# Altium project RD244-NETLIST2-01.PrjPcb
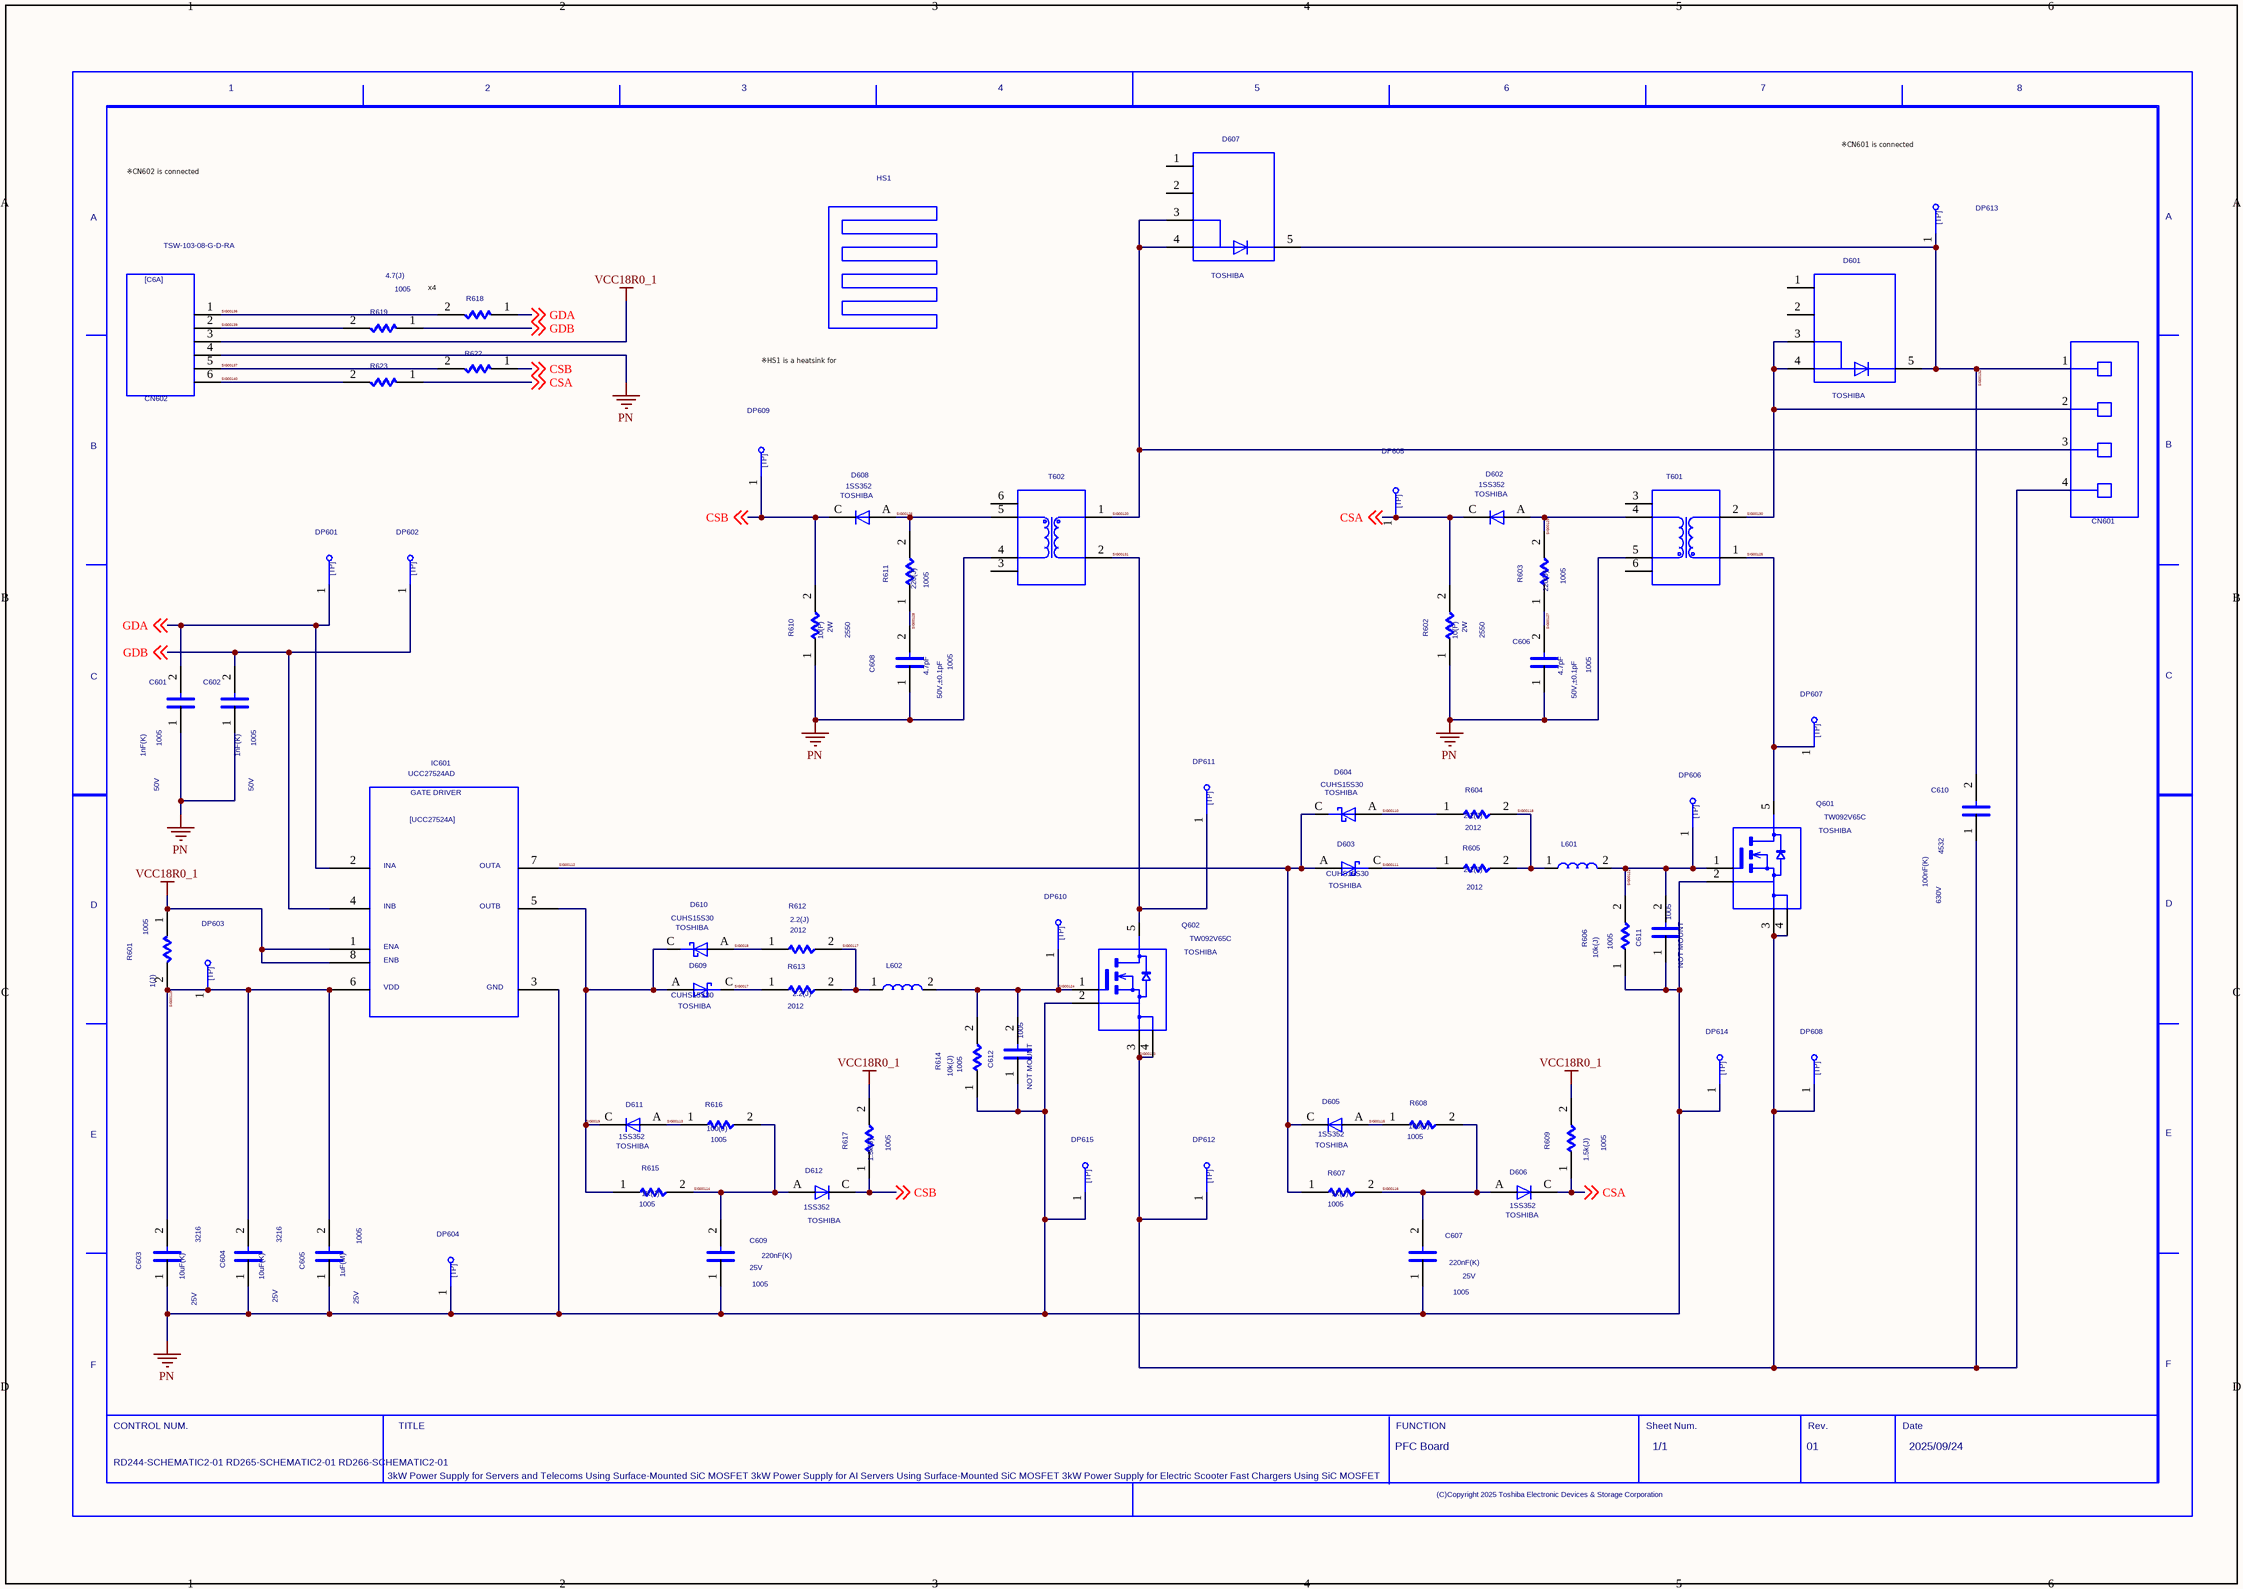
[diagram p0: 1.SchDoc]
1 sheet, 71 parts. Net scope: global (net labels, ports and power ports of the same name join across sheets).

## Sheet 1.SchDoc
size 420 x 297 mm

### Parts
C601  VAL1: 1nF(K)  VAL2: 50V  SIZECODESMD: 1005  (hidden comment: C)
C602  VAL1: 1nF(K)  VAL2: 50V  SIZECODESMD: 1005  (hidden comment: C)
C603  VAL1: 10uF(K)  VAL2: 25V  SIZECODESMD: 3216  (hidden comment: C)
C604  VAL1: 10uF(K)  VAL2: 25V  SIZECODESMD: 3216  (hidden comment: C)
C605  VAL1: 1uF(M)  VAL2: 25V  SIZECODESMD: 1005  (hidden comment: C)
C606  VAL1: 4.7pF  VAL2: 50V,±0.1pF  SIZECODESMD: 1005  (hidden comment: C)
C607  VAL1: 220nF(K)  VAL2: 25V  SIZECODESMD: 1005  (hidden comment: C)
C608  VAL1: 4.7pF  VAL2: 50V,±0.1pF  SIZECODESMD: 1005  (hidden comment: C)
C609  VAL1: 220nF(K)  VAL2: 25V  SIZECODESMD: 1005  (hidden comment: C)
C610  VAL1: 100nF(K)  VAL2: 630V  SIZECODESMD: 4532  (hidden comment: C)
C611  NOTMOUNT: NOT MOUNT  SIZECODESMD: 1005  (hidden comment: C)
C612  NOTMOUNT: NOT MOUNT  SIZECODESMD: 1005  (hidden comment: C)
CN601  RD-244_CN_from_PFC  (value not drawn)
CN602  VAL3: TSW-103-08-G-D-RA  (hidden comment: C6A)
D601  USERCOMPTEXT3: TOSHIBA  (hidden comment: TRS12V65H)
D602  USERCOMPTEXT3: TOSHIBA  VAL3: 1SS352  (hidden comment: D)
D603  USERCOMPTEXT3: TOSHIBA  (hidden comment: CUHS15S30)
D604  USERCOMPTEXT3: TOSHIBA  (hidden comment: CUHS15S30)
D605  USERCOMPTEXT3: TOSHIBA  VAL3: 1SS352  (hidden comment: D)
D606  USERCOMPTEXT3: TOSHIBA  VAL3: 1SS352  (hidden comment: D)
D607  USERCOMPTEXT3: TOSHIBA  (hidden comment: TRS12V65H)
D608  USERCOMPTEXT3: TOSHIBA  VAL3: 1SS352  (hidden comment: D)
D609  USERCOMPTEXT3: TOSHIBA  (hidden comment: CUHS15S30)
D610  USERCOMPTEXT3: TOSHIBA  (hidden comment: CUHS15S30)
D611  USERCOMPTEXT3: TOSHIBA  VAL3: 1SS352  (hidden comment: D)
D612  USERCOMPTEXT3: TOSHIBA  VAL3: 1SS352  (hidden comment: D)
DP601  TP  (value not drawn)
DP602  TP  (value not drawn)
DP603  TP  (value not drawn)
DP604  TP  (value not drawn)
DP605  TP  (value not drawn)
DP606  TP  (value not drawn)
DP607  TP  (value not drawn)
DP608  TP  (value not drawn)
DP609  TP  (value not drawn)
DP610  TP  (value not drawn)
DP611  TP  (value not drawn)
DP612  TP  (value not drawn)
DP613  TP  (value not drawn)
DP614  TP  (value not drawn)
DP615  TP  (value not drawn)
HS1  UB4060-12BM-1GG  (value not drawn)
IC601  VAL3: UCC27524AD  (hidden comment: L27524)
L601  L  (value not drawn)
L602  L  (value not drawn)
Q601  VAL3: TW092V65C  USERCOMPTEXT3: TOSHIBA  (hidden comment: NchMOSFET_DFN8x8-02)
Q602  VAL3: TW092V65C  USERCOMPTEXT3: TOSHIBA  (hidden comment: NchMOSFET_DFN8x8-02)
R601  VAL1: 1(J)  SIZECODESMD: 1005  (hidden comment: R)
R602  VAL2: 2W  USERCOMPTEXT1: 10(F)  SIZECODESMD: 2550  (hidden comment: R)
R603  VAL1: 220(J)  SIZECODESMD: 1005  (hidden comment: R)
R604  VAL1: 2.2(J)  SIZECODESMD: 2012  (hidden comment: R)
R605  VAL1: 2.2(J)  SIZECODESMD: 2012  (hidden comment: R)
R606  VAL1: 10k(J)  SIZECODESMD: 1005  (hidden comment: R)
R607  VAL1: 1k(J)  SIZECODESMD: 1005  (hidden comment: R)
R608  VAL1: 100(J)  SIZECODESMD: 1005  (hidden comment: R)
R609  VAL1: 1.5k(J)  SIZECODESMD: 1005  (hidden comment: R)
R610  VAL2: 2W  USERCOMPTEXT1: 10(F)  SIZECODESMD: 2550  (hidden comment: R)
R611  VAL1: 220(J)  SIZECODESMD: 1005  (hidden comment: R)
R612  VAL1: 2.2(J)  SIZECODESMD: 2012  (hidden comment: R)
R613  VAL1: 2.2(J)  SIZECODESMD: 2012  (hidden comment: R)
R614  VAL1: 10k(J)  SIZECODESMD: 1005  (hidden comment: R)
R615  VAL1: 1K(J)  SIZECODESMD: 1005  (hidden comment: R)
R616  VAL1: 100(J)  SIZECODESMD: 1005  (hidden comment: R)
R617  VAL1: 1.5k(J)  SIZECODESMD: 1005  (hidden comment: R)
R618  VAL1: 4.7(J)  SIZECODESMD: 1005  (hidden comment: R)
R619  R  (value not drawn)
R622  R  (value not drawn)
R623  R  (value not drawn)
T601  PH9505_100NLT  (value not drawn)
T602  PH9505_100NLT  (value not drawn)
U?  DATE: 2025/09/24  DRAWINGNUMBER: RD244-SCHEMATIC2-01 / RD265-SCHEMATIC2-01 / RD266-SCHEMATIC2-01  TITLE: 3kW Power Supply for Servers and Telecoms Using Surface-Mounted SiC MOSFET / 3kW Power Supply for AI Servers Using Surface-Mounted SiC MOSFET / 3kW Power Supply for Electric Scooter Fast Chargers Using SiC MOSFET  FUNCTION: PFC Board  SHEETNUMBER: 1/1  REVISION: 01  (hidden comment: WAKU_DEF100)

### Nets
PN: C601.1 C602.1 C603.1 C604.1 C605.1 C606.1 C607.1 C608.1 C609.1 C611.1 C612.1 CN602.4 DP604.1 DP614.1 DP615.1 IC601.3 Q601.2 Q602.2 R602.1 R606.1 R610.1 R614.1 T601.5 T602.4
VCC18R0_1: CN602.3 IC601.1 IC601.8 R601.1 R609.2 R617.2
CSA: D602.C D606.C DP605.1 R602.2 R609.1 R623.1 ; off-sheet CSA
CSB: D608.C D612.C DP609.1 R610.2 R617.1 R622.1 ; off-sheet CSB
GDA: C601.2 DP601.1 IC601.2 R618.1 ; off-sheet GDA
GDB: C602.2 DP602.1 IC601.4 R619.1 ; off-sheet GDB
SIG0017: D609.C R613.1
SIG0018: D610.A R612.1
SIG0019: D609.A D610.C D611.C IC601.5 R615.1
SIG00110: D604.A R604.1
SIG00111: D603.C R605.1
SIG00112: D603.A D604.C D605.C IC601.7 R607.1
SIG00113: D611.A R616.1
SIG00114: C609.2 D612.A R615.2 R616.2
SIG00115: D605.A R608.1
SIG00116: C607.2 D606.A R607.2 R608.2
SIG00117: L602.1 R612.2 R613.2
SIG00118: L601.1 R604.2 R605.2
SIG00119: C603.2 C604.2 C605.2 DP603.1 IC601.6 R601.2
SIG00120: CN601.3 D607.3 D607.4 T602.1
SIG00121: C611.2 DP606.1 L601.2 Q601.1 R606.2
SIG00124: C612.2 DP610.1 L602.2 Q602.1 R614.2
SIG00125: DP607.1 Q601.5 T601.1
SIG00126: D608.A R611.2 T602.5
SIG00127: C606.2 R603.1
SIG00128: C608.2 R611.1
SIG00129: D602.A R603.2 T601.4
SIG00130: CN601.2 D601.3 D601.4 T601.2
SIG00131: DP611.1 Q602.5 T602.2
SIG00132: C610.2 CN601.1 D601.5 D607.5 DP613.1
SIG00133: C610.1 CN601.4 DP608.1 DP612.1 Q601.3 Q601.4 Q602.3 Q602.4
SIG00136: CN602.1 R618.2
SIG00137: CN602.5 R622.2
SIG00139: CN602.2 R619.2
SIG00140: CN602.6 R623.2

Not connected (* = marked no-connect by the designer): D601 1 2; D607 1 2; T601 3 6; T602 3 6

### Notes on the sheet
- ※CN602 is connected
  to A51 of RD244-SCHEMATICS1
- ※CN601 is connected
  to A51 of RD244-SCHEMATICS1
- x4
- ※HS1 is a heatsink for
  Q601,Q602,D601 and D607

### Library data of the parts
C601 C602 = C_Dup1: OriginalSymbolOrigin: (2540,7620); COMP: PRT_52; VAL3: GRM155R71H102KA01; MAXGCOUNT: 1; SAVECOUNT: 0
C603 C604 = C_Dup1: OriginalSymbolOrigin: (2540,7620); COMP: PRT_46; VAL3: GRM31CR71E106KA12; MAXGCOUNT: 1; SAVECOUNT: 0
C605 = C_Dup1: OriginalSymbolOrigin: (2540,7620); COMP: PRT_52; VAL3: GRM155C81E105ME11; MAXGCOUNT: 1; SAVECOUNT: 0
C606 C608 = C_Dup1: OriginalSymbolOrigin: (2540,7620); COMP: PRT_52; VAL3: GRM1555C1H4R7BA01D; MAXGCOUNT: 1; SAVECOUNT: 0
C607 = C_Dup1: OriginalSymbolOrigin: (2540,7620); COMP: PRT_52; VAL3: GRM155C81E224KE01; MAXGCOUNT: 1; SAVECOUNT: 0
C609 = C_Dup1: SQ_PART_MODEL: CON_47N; OriginalSymbolOrigin: (2540,7620); COMP: PRT_52; VAL3: GRM155C81E224KE01; MAXGCOUNT: 1; ADSCNVFLAG: ON; ADSCOMPONENTNAME: C_1005; SAVECOUNT: 0
C610 = C: SQ_PART_MODEL: CON_100N; OriginalSymbolOrigin: (2540,7620); MAXGCOUNT: 1; COMP: K03S007Y; ADSCNVFLAG: ON; ADSCOMPONENTNAME: C_4532; VAL3: GRJ43DR72J104KWJ1K; SAVECOUNT: 0
C611 C612 = C_Dup1: VAL1: 1uF(M); VAL2: 25V; OriginalSymbolOrigin: (2540,7620); COMP: PRT_52; VAL3: GRM155C81E105ME11; MAXGCOUNT: 1; SAVECOUNT: 0
CN601 = RD-244_CN_FROM_PFC: TIME: 11:34:46; UPDATEUSER: t4887876; UPDATETIME: 21:48:48; SAVECOUNT: 35; SAVEAREA0: -20981,-344,43891,33349; VAL3: PCB_Pad; OriginalSymbolOrigin: (0,33020)
CN602 = C6A: OUMEPARTTYPE2: CN; SAVEAREA0: -13050,-324,32905,28692; SAVECOUNT: 22; TIME: 13:28:28; UPDATEUSER: tomizawa-y; UPDATETIME: 10:39:55; OriginalSymbolOrigin: (2540,25400); GATENO: 1; COMP: K22S0030; ADSCNVFLAG: ON
D601 D607 = TRS12V65H: SAVEAREA0: -33193,-13687,53697,33858; TIME: 14:49:55; UPDATEUSER: t4887876; UPDATETIME: 12:31:26; SAVECOUNT: 38; VAL1: 650V; VAL2: 12A; OriginalSymbolOrigin: (5080,20320); MAXGCOUNT: 1
D602 D605 D606 D608 D611 = D: SAVEAREA0: -225,-91,12804,7836; SAVECOUNT: 3; TIME: 14:49:55; UPDATEUSER: 19870035; UPDATETIME: 14:20:16; VAL1: 1SS352(TPH3,F); OriginalSymbolOrigin: (5080,5080); USERCOMPTEXT2: 80V,0.1A; COMP: PRT_27; MAXGCOUNT: 1
D603 D604 D609 D610 = CUHS15S30: SAVEAREA0: -4630,-153,17114,13055; TIME: 14:49:55; UPDATEUSER: t4887876; UPDATETIME: 17:19:09; SAVECOUNT: 10; OriginalSymbolOrigin: (5080,5080); USERCOMPTEXT2: 30V,1.5A; MAXGCOUNT: 1
D612 = D: SAVEAREA0: -225,-91,12804,7836; SAVECOUNT: 3; TIME: 14:49:55; UPDATEUSER: 19870035; UPDATETIME: 14:20:16; VAL1: 1SS352(TPH3,F); OriginalSymbolOrigin: (5080,5080); USERCOMPTEXT2: 80V,0.1A; COMP: PRT_27; MAXGCOUNT: 1; ADSCNVFLAG: ON; ADSCOMPONENTNAME: D_D
DP601-DP615 = TP: TIME: 16:12:21; UPDATEUSER: fukuda-y; UPDATETIME: 16:18:11; SAVECOUNT: 2; SAVEAREA0: -242,-92,12810,7836; OriginalSymbolOrigin: (0,7620); USERCOMPTEXT1: Φ1.5mm; COMP: DTP815
HS1 = UB4060-12BM-1GG: TIME: 14:03:26; UPDATEUSER: t4887876; UPDATETIME: 11:07:19; SAVECOUNT: 66; SAVEAREA0: -22316,-9081,43667,39223; VAL2: W40mm*L60mm*H12mm; OriginalSymbolOrigin: (5080,21590)
IC601 = L27524: SAVEAREA0: -24347,-591,50370,48694; SAVECOUNT: 22; TIME: 15:02:55; UPDATEUSER: cae; UPDATETIME: 14:54:38; OriginalSymbolOrigin: (7620,45720); COMP: PRT_63
L601 L602 = L: OriginalSymbolOrigin: (2540,5080); COMP: PRT_30; VAL3: LSMCC321611T800RG; SAVECOUNT: 0
Q601 Q602 = NCHMOSFET_DFN8X8-02: SAVECOUNT: 22; SAVEAREA0: -7027,-292,21786,15988; TIME: 18:23:27; UPDATEUSER: t5459927; UPDATETIME: 10:08:10; CHIPSET: DFN8x8; VAL2: ※定格電流を記入する; OriginalSymbolOrigin: (5080,22860)
R601 = R_Dup1: VAL2: 63mW; OriginalSymbolOrigin: (5080,5080); COMP: GDM010004481; VAL3: RK73B1ETTP1R0J; CHIPSIZE: 1608; MAXGCOUNT: 1; SAVECOUNT: 0
R602 R610 = R: SQ_PART_MODEL: RES_750; OriginalSymbolOrigin: (5080,5080); MAXGCOUNT: 1; COMP: K01S003U; ADSCNVFLAG: ON; ADSCOMPONENTNAME: R_2550; VAL3: WK73R2H2TTE7500F; SAVECOUNT: 0
R603 R611 = R_Dup1: VAL2: 63mW; OriginalSymbolOrigin: (5080,5080); COMP: GDM010004481; VAL3: RK73B1ETTP221J; CHIPSIZE: 1608; MAXGCOUNT: 1; SAVECOUNT: 0
R604 R605 R612 R613 = R_Dup1: VAL2: 250mW; OriginalSymbolOrigin: (5080,5080); COMP: R2012; VAL3: RK73B2ATTD2R2J; CHIPSIZE: 3216; MAXGCOUNT: 1; SAVECOUNT: 0
R606 R614 = R_Dup1: VAL2: 63mW; OriginalSymbolOrigin: (5080,5080); COMP: GDM010004481; VAL3: RK73B1ETTP103J; CHIPSIZE: 1608; MAXGCOUNT: 1; SAVECOUNT: 0
R607 = R_Dup1: SQ_PART_MODEL: RES_1.74K; VAL2: 63mW; OriginalSymbolOrigin: (5080,5080); COMP: GDM010004481; VAL3: RK73B1ETTP102J; CHIPSIZE: 1608; MAXGCOUNT: 1; ADSCNVFLAG: ON; ADSCOMPONENTNAME: R_1608; SAVECOUNT: 0
R608 R616 = R_Dup1: VAL2: 63mW; OriginalSymbolOrigin: (5080,5080); MAXGCOUNT: 1; VAL3: RK73B1ETTP101J; CHIPSIZE: 1608; COMP: GDM010004481; SAVECOUNT: 0
R609 R617 = R_Dup1: VAL2: 63mW; OriginalSymbolOrigin: (5080,5080); COMP: GDM010004481; VAL3: RK73B1ETTP152J; CHIPSIZE: 1608; MAXGCOUNT: 1; SAVECOUNT: 0
R615 = R_Dup1: VAL2: 63mW; OriginalSymbolOrigin: (5080,5080); COMP: GDM010004481; VAL3: RK73B1ETTP102J; CHIPSIZE: 1608; MAXGCOUNT: 1; SAVECOUNT: 0
R618 = R_Dup1: VAL2: 63mW; OriginalSymbolOrigin: (5080,5080); COMP: GDM010004481; VAL3: RK73B1ETTP4R7J; CHIPSIZE: 1608; MAXGCOUNT: 1; SAVECOUNT: 0
R619 = R_Dup1: VAL2: 63mW; VAL1: 4.7; OriginalSymbolOrigin: (5080,5080); COMP: GDM010004481; VAL3: RK73B1ETTP4R7J; CHIPSIZE: 1608; MAXGCOUNT: 1; SIZECODESMD: 1005; SAVECOUNT: 0
R622 R623 = R_Dup1: VAL2: 63mW; VAL1: 0; OriginalSymbolOrigin: (5080,5080); COMP: GDM010004481; VAL3: RK73Z1ETTP; CHIPSIZE: 1608; MAXGCOUNT: 1; SIZECODESMD: 1005
T601 T602 = PH9505_100NLT: TIME: 20:40:33; UPDATEUSER: t4887876; UPDATETIME: 09:36:55; SAVECOUNT: 7; VAL3: PH9505.100NLT; VAL1: 1:100; VAL2: 30A; OriginalSymbolOrigin: (5080,17780); MAXGCOUNT: 1
U? = WAKU_DEF100: PLOTTIME: HH:MM; SAVEAREA0: -63393,-16950,474261,314592; TIME: 14:30:25; UPDATEUSER: t5459927; UPDATETIME: 20:29:13; SAVECOUNT: 3; OriginalSymbolOrigin: (10160,284480); SHTSAVECOUNT: 186; PAGENUMBER: 2; DESIGNED: TOSHIBA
